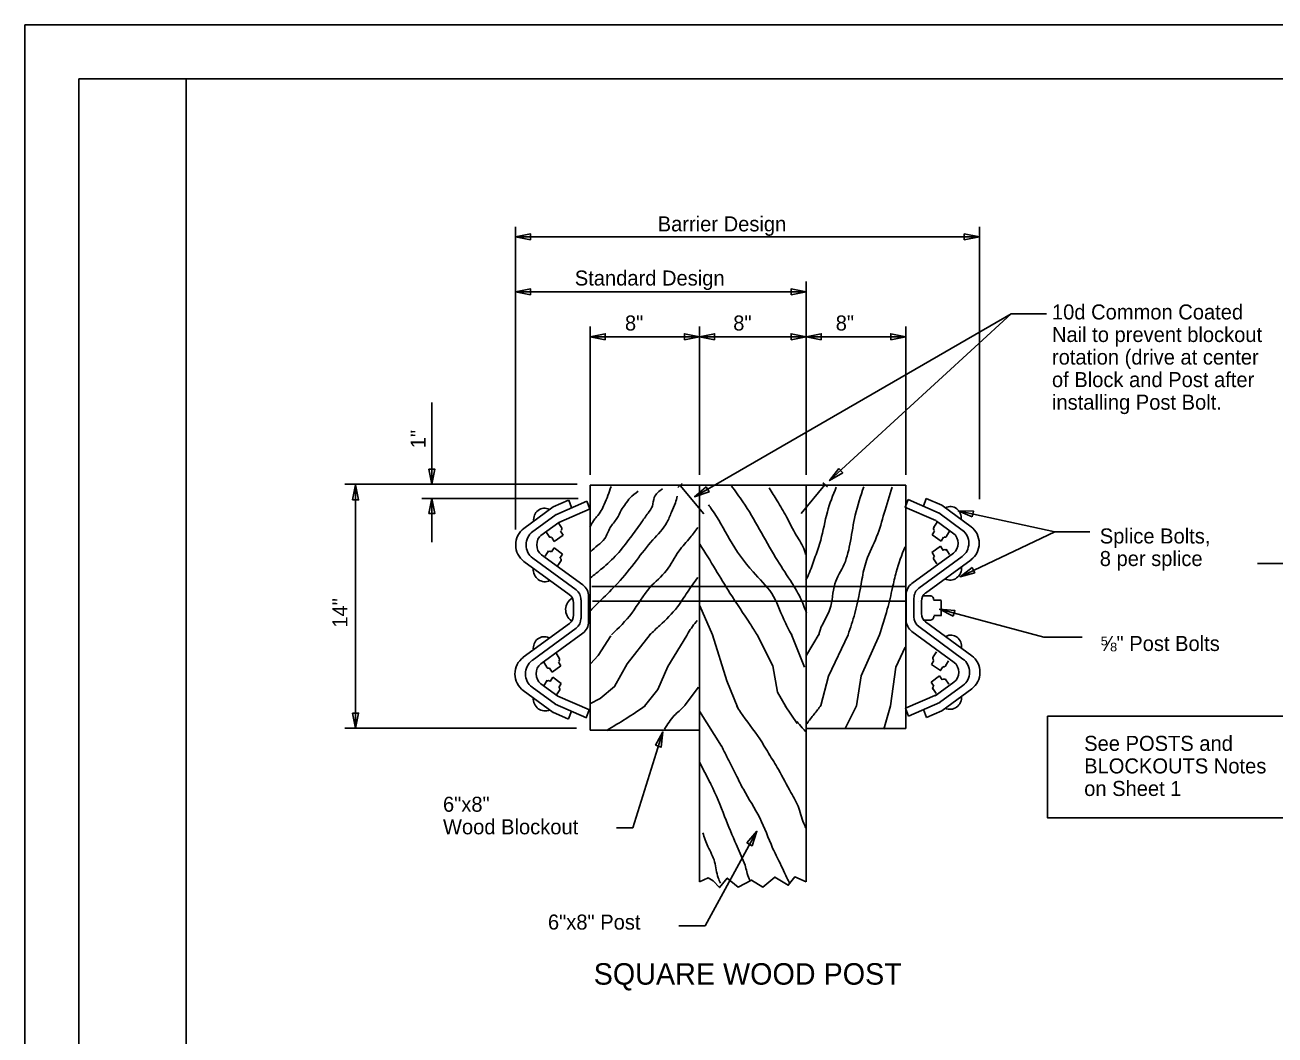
# Model space of a CAD drawing. Extents: x 0 to 34, y 0 to 22.
# Drawn here: x 0 to 11.64, y 12.6 to 22 of the extents above; entities that cross this region are included whole.
import ezdxf

# ---------------------------------------------------------------- set-up
doc = ezdxf.new("R2010")
doc.units = 0
for name, color, linetype in [('SH_Border', 7, 'Continuous'), ('SH_Cut_Line', 7, 'Continuous'), ('ST_Details', 7, 'Continuous'), ('ST_Text', 7, 'Continuous')]:
    doc.layers.add(name, color=color, linetype=linetype)

msp = doc.modelspace()

# ---------------------------------------------------------------- linework, layer by layer
at = {"layer": 'SH_Border'}
for points in [[(0.5, 21.5), (1.5, 21.5), (1.5, 0.5), (0.5, 0.5)], [(1.5, 21.5), (33.5, 21.5), (33.5, 0.5), (1.5, 0.5)]]:
    msp.add_lwpolyline(points, close=True, dxfattribs=at)
at = {"layer": 'SH_Cut_Line'}
msp.add_lwpolyline([(0, 0), (34, 0), (34, 22), (0, 22)], close=True, dxfattribs=at)
at = {"layer": 'ST_Details'}
for p, q in [((5.261, 17.716), (8.2, 17.716)), ((5.261, 17.716), (5.261, 15.435)), ((6.117, 17.731), (6.076, 17.694)), ((6.099, 17.712), (6.32, 17.447)), ((6.279, 17.716), (6.279, 14.022)), ((7.446, 17.717), (7.226, 17.452)), ((7.271, 17.716), (7.271, 14.022)), ((7.428, 17.736), (7.469, 17.699)), ((8.2, 17.716), (8.2, 15.448)), ((4.916, 17.513), (5.06, 17.576)), ((5.088, 17.506), (5.061, 17.575)), ((8.194, 17.511), (8.221, 17.581)), ((8.51, 17.455), (8.22, 17.582)), ((8.363, 17.521), (8.39, 17.59)), ((8.534, 17.528), (8.39, 17.591)), ((4.917, 17.513), (4.644, 17.313)), ((4.941, 17.44), (5.231, 17.566)), ((4.97, 17.369), (5.26, 17.496)), ((5.257, 17.496), (5.23, 17.565)), ((8.48, 17.385), (8.191, 17.511)), ((8.507, 17.457), (8.737, 17.288)), ((8.534, 17.528), (8.807, 17.328)), ((4.944, 17.441), (4.714, 17.273)), ((4.969, 17.369), (4.803, 17.247)), ((4.994, 17.321), (4.964, 17.368)), ((8.461, 17.323), (8.491, 17.37)), ((8.481, 17.384), (8.648, 17.262)), ((4.878, 17.238), (4.849, 17.284)), ((4.927, 17.192), (4.904, 17.228)), ((4.927, 17.192), (5.009, 17.251)), ((5.009, 17.251), (4.986, 17.286)), ((8.446, 17.253), (8.468, 17.288)), ((8.528, 17.194), (8.446, 17.253)), ((8.528, 17.194), (8.551, 17.23)), ((8.577, 17.24), (8.606, 17.286)), ((4.901, 17.093), (4.926, 17.132)), ((5.004, 17.074), (4.925, 17.131)), ((8.443, 17.089), (8.522, 17.146)), ((8.546, 17.108), (8.522, 17.147)), ((8.606, 17.068), (8.575, 17.118)), ((5.067, 16.696), (4.644, 17.004)), ((5.131, 16.741), (4.727, 17.035)), ((5.194, 16.786), (4.809, 17.066)), ((4.841, 17.053), (4.873, 17.103)), ((4.959, 16.967), (4.99, 17.015)), ((4.98, 17.035), (5.004, 17.073)), ((8.257, 16.801), (8.642, 17.081)), ((8.32, 16.756), (8.724, 17.05)), ((8.383, 16.711), (8.807, 17.019)), ((8.468, 17.051), (8.444, 17.088)), ((8.488, 16.982), (8.457, 17.03)), ((5.276, 16.77), (8.201, 16.77)), ((5.176, 16.475), (5.176, 16.648)), ((5.247, 16.445), (5.247, 16.678)), ((8.203, 16.46), (8.203, 16.693)), ((8.274, 16.49), (8.274, 16.663)), ((8.361, 16.684), (8.433, 16.684)), ((8.456, 16.643), (8.529, 16.643)), ((8.529, 16.503), (8.529, 16.642)), ((5.106, 16.504), (5.106, 16.618)), ((5.176, 16.556), (5.176, 16.567)), ((5.284, 16.634), (8.197, 16.634)), ((6.282, 16.59), (6.399, 16.321)), ((8.274, 16.571), (8.274, 16.582)), ((8.317, 16.632), (8.317, 16.632)), ((8.345, 16.519), (8.345, 16.634)), ((5.068, 16.427), (4.637, 16.112)), ((8.362, 16.459), (8.424, 16.459)), ((8.383, 16.442), (8.814, 16.127)), ((8.459, 16.503), (8.533, 16.503)), ((5.131, 16.382), (4.72, 16.081)), ((5.194, 16.337), (4.802, 16.05)), ((7.133, 16.33), (7.256, 16.019)), ((7.393, 16.33), (7.274, 16.133)), ((8.257, 16.353), (8.649, 16.065)), ((8.32, 16.398), (8.731, 16.096)), ((4.858, 16.02), (4.829, 16.066)), ((4.974, 16.103), (4.944, 16.15)), ((4.989, 16.033), (4.967, 16.068)), ((8.438, 16.046), (8.461, 16.082)), ((8.453, 16.116), (8.484, 16.163)), ((8.569, 16.034), (8.598, 16.079)), ((4.907, 15.974), (4.884, 16.01)), ((4.907, 15.974), (4.989, 16.033)), ((8.521, 15.988), (8.438, 16.046)), ((8.52, 15.987), (8.544, 16.023)), ((4.938, 15.675), (4.72, 15.834)), ((4.96, 15.75), (4.802, 15.865)), ((4.829, 15.848), (4.86, 15.898)), ((4.889, 15.888), (4.913, 15.927)), ((4.992, 15.869), (4.913, 15.927)), ((4.968, 15.831), (4.991, 15.868)), ((6.146, 15.669), (6.269, 15.835)), ((8.436, 15.882), (8.514, 15.94)), ((8.46, 15.844), (8.436, 15.881)), ((8.473, 15.753), (8.648, 15.88)), ((8.513, 15.691), (8.731, 15.849)), ((8.539, 15.901), (8.514, 15.94)), ((8.599, 15.861), (8.567, 15.911)), ((4.917, 15.599), (4.638, 15.803)), ((4.947, 15.762), (4.978, 15.81)), ((4.96, 15.751), (5.254, 15.623)), ((5.259, 15.678), (5.354, 15.729)), ((8.491, 15.766), (8.197, 15.638)), ((8.481, 15.775), (8.45, 15.823)), ((8.534, 15.615), (8.813, 15.818)), ((4.915, 15.6), (5.059, 15.537)), ((5.226, 15.549), (4.936, 15.676)), ((5.058, 15.538), (5.086, 15.61)), ((5.225, 15.549), (5.253, 15.623)), ((6.485, 15.285), (6.278, 15.611)), ((7.077, 15.66), (7.188, 15.495)), ((7.634, 15.448), (7.739, 15.66)), ((7.994, 15.444), (8.057, 15.66)), ((8.226, 15.565), (8.197, 15.638)), ((8.225, 15.565), (8.515, 15.691)), ((8.393, 15.553), (8.365, 15.626)), ((8.536, 15.615), (8.392, 15.553)), ((5.261, 15.435), (6.278, 15.435)), ((7.27, 15.448), (8.199, 15.448)), ((6.278, 15.137), (6.379, 14.944)), ((6.619, 14.373), (6.703, 14.178))]:
    msp.add_line(p, q, dxfattribs=at)
for points in [[(5.453, 16.313), (5.335, 16.129), (5.264, 16.05)], [(5.819, 16.325), (5.607, 16.05), (5.488, 15.839), (5.354, 15.729)], [(6.16, 16.315), (5.984, 16.028), (5.892, 15.813), (5.768, 15.656)], [(6.399, 16.321), (6.532, 15.892), (6.637, 15.642)], [(6.816, 16.321), (6.962, 16.032), (7.006, 15.787), (7.086, 15.647)], [(7.662, 16.321), (7.48, 15.936), (7.409, 15.665)], [(7.955, 16.321), (7.783, 15.94), (7.739, 15.66)], [(8.057, 15.66), (8.107, 16.019), (8.195, 16.208)], [(6.279, 14.022), (6.36, 14.06), (6.406, 14.03), (6.464, 13.968), (6.538, 14.056), (6.638, 13.973), (6.762, 14.038), (6.869, 13.973), (6.981, 14.065), (7.105, 13.99), (7.167, 14.069), (7.271, 14.022)]]:
    msp.add_lwpolyline(points, dxfattribs=at)
for centre, major_axis, start_param, end_param in [((4.836, 17.394), (0, -0.107), 2.687211, 4.851441), ((8.614, 17.409), (0, -0.107), 1.431744, 3.595974), ((4.745, 17.159), (0, -0.187), 3.747084, 5.680264), ((4.807, 17.159), (0, -0.15), 3.747137, 5.680324), ((4.869, 17.159), (0, -0.112), 3.747102, 5.680297), ((4.891, 17.249), (0, -0.0195), 5.247458, 6.879592), ((4.978, 17.309), (0, 0.0198), 3.70437, 5.352473), ((8.477, 17.311), (0, 0.0198), 0.930712, 2.578815), ((8.564, 17.251), (0, -0.0195), 5.686779, 7.318912), ((8.582, 17.174), (0, -0.112), 0.602888, 2.536083), ((8.644, 17.174), (0, -0.15), 0.602861, 2.536048), ((8.706, 17.174), (0, -0.187), 0.602921, 2.536101), ((8.562, 17.095), (0, 0.021), 5.448045, 7.11407), ((4.885, 17.079), (0, 0.021), 5.452301, 7.118326), ((4.971, 17.017), (0, 0.021), 4.196406, 5.73538), ((8.477, 17.032), (0, 0.021), 0.547805, 2.086779), ((4.84, 16.931), (0, -0.115), 4.640651, 6.714317), ((8.611, 16.946), (0, -0.115), 5.852054, 7.925719), ((5.123, 16.678), (0, 0.131), 4.712389, 5.680267), ((8.327, 16.693), (0, 0.131), 0.602918, 1.570796), ((5.146, 16.556), (0, -0.12), 3.613765, 5.74142), ((5.017, 16.619), (0, 0.0937), 4.712389, 5.680377), ((5.07, 16.648), (0, 0.112), 4.712389, 5.68034), ((8.381, 16.663), (0, 0.112), 0.602846, 1.570796), ((8.434, 16.634), (0, 0.0937), 0.602808, 1.570796), ((8.431, 16.654), (0, -0.0298), 2.729343, 3.43401), ((8.43, 16.654), (0, 0.03), 4.574534, 6.237266), ((8.431, 16.654), (0, -0.0298), 1.431351, 1.439211), ((5.017, 16.504), (0, -0.0937), 0.605563, 1.570796), ((5.07, 16.475), (0, -0.112), 0.605651, 1.570796), ((5.123, 16.445), (0, -0.131), 0.605566, 1.570796), ((8.327, 16.46), (0, -0.131), 4.712389, 5.677619), ((8.381, 16.49), (0, -0.112), 4.712389, 5.677535), ((8.434, 16.519), (0, -0.0937), 4.712389, 5.677623), ((8.429, 16.491), (0, -0.0326), 6.093782, 8.000338), ((4.833, 16.197), (0, -0.107), 2.687211, 4.851441), ((8.618, 16.212), (0, -0.107), 1.431744, 3.595974), ((4.738, 15.957), (0, -0.187), 3.747091, 5.68028), ((4.8, 15.958), (0, -0.15), 3.747115, 5.680355), ((4.958, 16.091), (0, 0.0198), 3.70437, 5.352473), ((8.469, 16.104), (0, 0.0198), 0.930712, 2.578815), ((8.588, 15.973), (0, -0.112), 0.602927, 2.536083), ((8.651, 15.973), (0, -0.15), 0.602831, 2.53607), ((8.713, 15.973), (0, -0.187), 0.602905, 2.536094), ((4.863, 15.958), (0, -0.112), 3.747102, 5.680258), ((4.871, 16.031), (0, -0.0195), 5.247458, 6.879592), ((8.556, 16.044), (0, -0.0195), 5.686779, 7.318912), ((4.873, 15.875), (0, 0.021), 5.452301, 7.118326), ((4.959, 15.812), (0, 0.021), 4.196406, 5.73538), ((8.469, 15.825), (0, 0.021), 0.547805, 2.086779), ((8.555, 15.888), (0, 0.021), 5.448045, 7.11407), ((4.84, 15.728), (0, -0.115), 4.640651, 6.714317), ((8.611, 15.743), (0, -0.115), 5.852054, 7.925719)]:
    msp.add_ellipse(centre, major_axis=major_axis, ratio=0.944544, start_param=start_param, end_param=end_param, dxfattribs=at)
for points in [[(5.456, 17.702), (5.393, 17.536), (5.364, 17.478), (5.321, 17.42), (5.292, 17.382), (5.259, 17.324)], [(6.577, 17.707), (6.682, 17.561), (6.838, 17.303), (6.987, 17.042), (7.125, 16.826), (7.216, 16.669), (7.274, 16.526)], [(6.926, 17.69), (7.002, 17.569), (7.089, 17.419), (7.18, 17.249), (7.256, 17.107), (7.267, 17.069)], [(7.552, 17.698), (7.469, 17.466), (7.407, 17.203), (7.357, 17.05), (7.303, 16.901), (7.27, 16.831)], [(7.808, 17.7), (7.729, 17.435), (7.684, 17.194), (7.626, 16.98), (7.539, 16.796), (7.493, 16.56), (7.394, 16.337), (7.391, 16.321)], [(8.071, 17.698), (7.998, 17.453), (7.928, 17.234), (7.833, 17.015), (7.791, 16.836), (7.725, 16.52), (7.662, 16.321)], [(5.263, 16.851), (5.372, 16.94), (5.51, 17.07), (5.637, 17.228), (5.735, 17.363), (5.8, 17.455), (5.84, 17.52), (5.858, 17.601), (5.935, 17.682)], [(5.263, 17.094), (5.332, 17.155), (5.397, 17.217), (5.448, 17.32), (5.51, 17.405), (5.55, 17.482), (5.59, 17.54), (5.633, 17.597), (5.709, 17.658)], [(5.266, 16.547), (5.364, 16.647), (5.517, 16.801), (5.691, 17.013), (5.844, 17.205), (5.975, 17.367), (6.018, 17.463), (6.055, 17.551), (6.072, 17.613)], [(6.362, 17.533), (6.392, 17.492), (6.559, 17.211), (6.777, 16.907), (6.951, 16.707), (7.064, 16.465), (7.137, 16.321)], [(5.459, 16.321), (5.648, 16.524), (5.818, 16.763), (5.971, 16.92), (6.087, 17.101), (6.193, 17.228), (6.262, 17.32)], [(6.283, 17.165), (6.428, 16.93), (6.562, 16.711), (6.751, 16.423), (6.816, 16.321)], [(7.955, 16.321), (8.027, 16.56), (8.076, 16.761), (8.11, 16.906), (8.192, 17.142)], [(5.815, 16.321), (5.909, 16.409), (6.073, 16.582), (6.167, 16.72), (6.262, 16.855)], [(6.16, 16.315), (6.174, 16.34), (6.258, 16.455)], [(5.415, 15.432), (5.593, 15.54), (5.773, 15.66)], [(5.953, 15.443), (6.044, 15.57), (6.134, 15.655), (6.151, 15.675)], [(6.625, 15.66), (6.662, 15.601), (6.84, 15.352), (6.933, 15.199)], [(7.409, 15.665), (7.378, 15.623), (7.312, 15.54), (7.278, 15.492)], [(7.184, 15.515), (7.234, 15.457), (7.271, 15.415)], [(6.484, 15.287), (6.551, 15.15), (6.626, 15.003)], [(6.924, 15.214), (7.014, 15.067), (7.13, 14.853), (7.204, 14.708), (7.258, 14.546), (7.27, 14.524)], [(6.375, 14.951), (6.385, 14.931), (6.513, 14.629), (6.622, 14.365)], [(6.627, 15.001), (6.687, 14.883), (6.84, 14.616), (6.96, 14.336), (7.051, 14.148), (7.092, 14.06), (7.121, 14.003)], [(6.309, 14.478), (6.358, 14.351), (6.42, 14.207), (6.453, 14.058), (6.474, 14.01)], [(6.703, 14.178), (6.741, 14.051), (6.753, 14.025)]]:
    msp.add_spline(points, degree=3, dxfattribs=at)
at = {"layer": 'ST_Text'}
for p, q in [((4.567, 20.121), (4.567, 17.7)), ((4.567, 20.027), (7.282, 20.027)), ((7.282, 20.027), (8.884, 20.027)), ((8.884, 20.121), (8.884, 17.585)), ((7.272, 19.61), (7.272, 19.064)), ((7.272, 19.61), (7.272, 17.81)), ((4.567, 19.515), (6.666, 19.515)), ((6.666, 19.515), (7.272, 19.515)), ((7.49, 17.757), (9.181, 19.312)), ((9.181, 19.312), (9.508, 19.312)), ((5.261, 17.81), (5.261, 19.191)), ((8.2, 19.097), (5.261, 19.097)), ((6.279, 17.81), (6.279, 19.191)), ((8.2, 17.81), (8.2, 19.191)), ((3.788, 18.484), (3.788, 17.723)), ((2.978, 17.723), (5.139, 17.723)), ((3.077, 17.718), (3.077, 16.996)), ((4.567, 17.7), (4.567, 17.569)), ((3.694, 17.592), (5.149, 17.592)), ((3.788, 17.592), (3.788, 17.183)), ((4.567, 17.569), (4.567, 17.303)), ((8.687, 17.475), (9.587, 17.282)), ((8.704, 16.862), (9.587, 17.282)), ((9.587, 17.282), (9.912, 17.282)), ((3.077, 16.996), (3.077, 15.453)), ((8.514, 16.559), (9.485, 16.299)), ((9.841, 16.299), (9.485, 16.299)), ((2.978, 15.453), (5.135, 15.453)), ((5.939, 15.417), (5.659, 14.523)), ((5.659, 14.523), (5.507, 14.523)), ((6.332, 13.611), (6.814, 14.493)), ((6.332, 13.611), (6.085, 13.611))]:
    msp.add_line(p, q, dxfattribs=at)
for points in [[(4.707, 19.999), (4.567, 20.027), (4.707, 20.055)], [(8.744, 19.999), (8.884, 20.027), (8.744, 20.055)], [(4.707, 19.487), (4.567, 19.515), (4.707, 19.543)], [(7.132, 19.487), (7.272, 19.515), (7.132, 19.543)], [(5.401, 19.069), (5.261, 19.097), (5.401, 19.125)], [(6.139, 19.069), (6.279, 19.097), (6.139, 19.125)], [(6.419, 19.069), (6.279, 19.097), (6.419, 19.125)], [(7.132, 19.069), (7.272, 19.097), (7.132, 19.125)], [(7.412, 19.069), (7.272, 19.097), (7.412, 19.125)], [(8.06, 19.069), (8.2, 19.097), (8.06, 19.125)], [(3.76, 17.863), (3.788, 17.723), (3.816, 17.863)], [(7.575, 17.871), (7.49, 17.757), (7.613, 17.83)], [(3.049, 17.578), (3.077, 17.718), (3.105, 17.578)], [(6.34, 17.701), (6.233, 17.607), (6.368, 17.652)], [(3.76, 17.452), (3.788, 17.592), (3.816, 17.452)], [(8.818, 17.419), (8.687, 17.475), (8.829, 17.474)], [(8.818, 16.949), (8.704, 16.862), (8.842, 16.899)], [(8.641, 16.494), (8.514, 16.559), (8.656, 16.548)], [(3.049, 15.593), (3.077, 15.453), (3.105, 15.593)], [(9.52, 15.565), (12.305, 15.565), (12.305, 14.616), (9.52, 14.616)], [(5.869, 15.293), (5.939, 15.417), (5.922, 15.275)], [(6.719, 14.386), (6.814, 14.493), (6.768, 14.358)]]:
    msp.add_lwpolyline(points, close=True, dxfattribs=at)
for points in [[(6.233, 17.607), (9.181, 19.312)], [(13.304, 17.476), (11.724, 16.986), (11.473, 16.986)]]:
    msp.add_lwpolyline(points, dxfattribs=at)

# ---------------------------------------------------------------- texts
for s, height, p in [('Barrier Design', 0.14, (5.89, 20.078)), ('Standard Design', 0.14, (5.118, 19.574)), ('10d Common Coated', 0.14, (9.56, 19.258)), ('  8"', 0.14, (5.481, 19.155)), ('  8"', 0.14, (6.489, 19.155)), ('  8"', 0.14, (7.443, 19.155)), ('Nail to prevent blockout', 0.14, (9.56, 19.048)), ('rotation (drive at center', 0.14, (9.56, 18.838)), ('of Block and Post after', 0.14, (9.56, 18.628)), ('installing Post Bolt.', 0.14, (9.56, 18.418)), ('Splice Bolts,', 0.14, (10.005, 17.172)), ('8 per splice', 0.14, (10.005, 16.962)), ('⅝" Post Bolts', 0.14, (10.005, 16.171)), ('See POSTS and', 0.14, (9.86, 15.241)), ('BLOCKOUTS Notes', 0.14, (9.86, 15.031)), ('on Sheet 1', 0.14, (9.86, 14.821)), ('6"x8"', 0.14, (3.891, 14.674)), ('Wood Blockout', 0.14, (3.891, 14.464)), ('6"x8" Post', 0.14, (4.868, 13.577)), ('SQUARE WOOD POST', 0.2, (5.294, 13.064))]:
    msp.add_text(s, height=height, dxfattribs=at).set_placement(p)
for s, p in [('1"', (3.729, 18.059)), ('14" ', (3.002, 16.388))]:
    msp.add_text(s, height=0.14, rotation=90, dxfattribs=at).set_placement(p)

doc.saveas('drawing.dxf')
